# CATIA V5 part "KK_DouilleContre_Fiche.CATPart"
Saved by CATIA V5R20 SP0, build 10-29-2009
Part number: Douille contre fiche
Bounding box of the stored display mesh (mm): x -2496 to -1872, y 896.032 to 1215.968, z -479.968 to -160.032
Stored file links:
  G:\Khaled_CFAO_2011\ST2M\ST2M_GR2\aboulegue\Khaled\CAD_thinkMOTION\KK_DouilleContre_Fiche.CATPart
  G:\Khaled_CFAO_2011\ST2M\ST2M_GR2\aboulegue\Khaled\CAD_thinkMOTION\KK_Train_Atterrissage.CATProduct
  G:\Khaled_CFAO_2011\ST2M\ST2M_GR2\aboulegue\Khaled\CAD_thinkMOTION\KK_SqueletteDouille_ContreFiche.CATPart
  G:\Khaled_CFAO_2011\ST2M\ST2M_GR2\aboulegue\Khaled\CAD_thinkMOTION\KK_SqueletteBati_Avion.CATPart
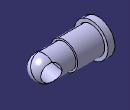
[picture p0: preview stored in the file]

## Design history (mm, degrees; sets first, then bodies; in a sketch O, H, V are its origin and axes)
External parameters (linked from other documents)
  `External.Longueur contre fiche superieure` = 1280 mm
Set1
  Plane1 "Plan douille contre fiche": linked copy from another document
  Line1: linked copy from another document
  Point1 "Point.18": linked copy from another document
  Point2 "Point.12": linked copy from another document
  Line2: linked copy from another document
  Line3: linked copy from another document
Body1 (main body)
  Sketch1 on Plane1, origin (0, 1056, 0), H (-1, 0, 0), V (0, 0, 1)
    line L1 (2496, -160) -> (2432, -160)
    line L2 (2432, -160) -> (2432, -192)
    line L3 (2432, -192) -> (2176, -192)
    line L4 (2176, -192) -> (2176, -320)
    line L5 (2176, -320) -> (2496, -320)
    point P6 (2496, -320)
    line L6 (2496, -320) -> (2496, -160)
    reference projected line E1 (2496, -320) -> (1984, -320) from Line1
    reference projected point E2 (2496, -320) from Point1
    reference projected line E3 (2496, 600) -> (2496, -320) from Line3
    length L5 = 320 {= 320mm*(`External.Longueur contre fiche superieure` /1280mm)}
    length L1 = 64 {= 64mm*(`External.Longueur contre fiche superieure` /1280mm)}
    length L2 = 32 {= 32mm*(`External.Longueur contre fiche superieure` /1280mm)}
    length L6 = 160 {= 160mm*(`External.Longueur contre fiche superieure` /1280mm)}
    horizontal: L1 H, L3 H, L5 H
    vertical: L2 V, L4 V
    coincidence: E1 L5, P6 E2, E3 L6
  Shaft1: profile Sketch1, axis Line1, angle 360
  Sketch2 on Plane1, origin (0, 1056, 0), H (-1, 0, 0), V (0, 0, 1)
    line L1 (2176, -208) -> (1984, -208)
    arc A1 centre (1984, -320) radius 112 from (1984, -208) to (1872, -320) ccw
    point P3 (1984, -320)
    line L2 (1872, -320) -> (2176, -320)
    line L3 (2176, -320) -> (2176, -208)
    reference projected line E1 (2496, -320) -> (1984, -320) from Line1
    reference projected line E2 (2176, -448) -> (2176, -192) from edge [face of Shaft1 from Sketch1.L3 | face of Shaft1 from Sketch1.L4]
    reference projected line E3 (2496, -320) -> (1984, -320) from Line1
    length L1 = 192 {= 192mm*(`External.Longueur contre fiche superieure` /1280mm)}
    radius A1 = 112 {= 112mm*(`External.Longueur contre fiche superieure` /1280mm)}
    horizontal: L1 H, L2 H
    tangency: A1 L1
    vertical: L3 V
    coincidence: L2 E1, L3 E2, P3 E3
  Shaft2: profile Sketch2, axis Line1, angle 360
  Sketch3 on Plane1, origin (0, 1056, 0), H (-1, 0, 0), V (0, 0, 1)
    circle A1 centre (1984, -320) radius 80
    point P1 (1984, -320)
    reference projected point E1 (1984, -320) from Point2
    radius A1 = 80
    coincidence: E1 P1
  Pocket1: profile Sketch3, direction along Line2, length 120, mirrored extent
  Sketch4 on face of Shaft1 from Sketch1.L6, origin (-2496, 0, 0), H (0, -1, 0), V (0, 0, 1)
    circle A1 centre (-1056, -320) radius 96
    point P1 (-1056, -320)
    reference projected point E1 (-1056, -320) from Point1
    radius A1 = 96
    coincidence: E1 P1
  Pocket2: profile Sketch4, direction (1, 0, 0), length 256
